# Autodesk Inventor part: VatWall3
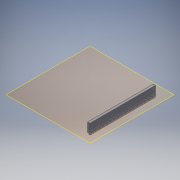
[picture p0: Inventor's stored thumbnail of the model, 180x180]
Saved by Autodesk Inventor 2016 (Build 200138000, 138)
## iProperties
Created: 2015-11
Part Number: VatWall3
Material: Generic
Document SubType Name: Modeling
Designer: John
Density: 1 g/cm^3
Appearance: Default
Author: John
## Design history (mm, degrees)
workplane "Work Plane1"
sketch "Sketch1"
  geometry: L1 (-103.475, 98.475)-(-103.475, -98.475) reference; L2 (-98.475, -103.475)-(98.475, -103.475) reference; L3 (103.475, -98.475)-(103.475, 98.475) reference; L4 (98.475, 103.475)-(-98.475, 103.475) reference; L5 (92.15, 92.15)-(92.15, -92.15) reference; L6 (92.15, -92.15)-(-92.15, -92.15) reference; L7 (-92.15, -92.15)-(-92.15, 92.15) reference; L8 (-92.15, 92.15)-(92.15, 92.15) reference; L9 (88.65, -88.65)-(88.65, 88.65) reference; L10 (88.65, 88.65)-(-88.65, 88.65) reference; L11 (-88.65, 88.65)-(-88.65, -88.65) reference; L12 (-88.65, -88.65)-(88.65, -88.65) reference; L13 (82.3, -85.475)-(-82.3, -85.475) reference; L14 (-85.475, -82.3)-(-85.475, 82.3) reference; L15 (-82.3, 85.475)-(82.3, 85.475) reference; L16 (85.475, 82.3)-(85.475, -82.3) reference; L17 (92.15, 92.15)-(88.65, 92.15); L18 (88.65, 92.15)-(88.65, -92.15); L19 (88.65, -92.15)-(92.15, -92.15); L20 (92.15, -92.15)-(92.15, 92.15); L21 (88.812, -91.988)-(88.812, 91.988); L22 (88.812, 91.988)-(91.987, 91.988); L23 (91.987, 91.988)-(91.987, -91.988); L24 (91.987, -91.988)-(88.812, -91.988); C1 r 1.75 at (-95, 44.824) reference; C2 r 1.75 at (-95, 59.766) reference; C3 r 1.75 at (-95, 29.886) reference; C4 r 1.75 at (-95, -0.002) reference; C5 r 1.75 at (-95, -29.886) reference; C6 r 1.75 at (-95, -59.77) reference; C7 r 1.75 at (-95, -74.708) reference; C8 r 1.75 at (-94.65, 94.65) reference; C9 r 1.75 at (-95, 74.708) reference; C10 r 1.75 at (-95, -44.828) reference; C11 r 1.75 at (-95, -14.944) reference; C12 r 1.75 at (-95, 14.944) reference; C13 r 1.75 at (44.824, 95) reference; C14 r 1.75 at (59.766, 95) reference; C15 r 1.75 at (29.886, 95) reference; C16 r 1.75 at (-0.002, 95) reference; C17 r 1.75 at (-29.886, 95) reference; C18 r 1.75 at (-59.77, 95) reference; C19 r 1.75 at (-74.708, 95) reference; C20 r 1.75 at (74.708, 95) reference; C21 r 1.75 at (-44.828, 95) reference; C22 r 1.75 at (-14.944, 95) reference; C23 r 1.75 at (14.944, 95) reference; C24 r 1.75 at (-14.944, -95) reference; C25 r 1.75 at (14.944, -95) reference; C26 r 1.75 at (44.828, -95) reference; C27 r 1.75 at (-74.708, -95) reference; C28 r 1.75 at (-94.65, -94.65) reference; C29 r 1.75 at (74.708, -95) reference; C30 r 1.75 at (59.77, -95) reference; C31 r 1.75 at (29.886, -95) reference; C32 r 1.75 at (0.002, -95) reference; C33 r 1.75 at (-29.886, -95) reference; C34 r 1.75 at (-59.766, -95) reference; C35 r 1.75 at (-44.824, -95) reference; C36 r 1.75 at (95, -44.824) reference; C37 r 1.75 at (95, -59.766) reference; C38 r 1.75 at (95, -29.886) reference; C39 r 1.75 at (95, 0.002) reference; C40 r 1.75 at (95, 29.886) reference; C41 r 1.75 at (95, 59.77) reference; C42 r 1.75 at (95, 74.708) reference; C43 r 1.75 at (94.65, -94.65) reference; C44 r 1.75 at (94.65, 94.65) reference; C45 r 1.75 at (95, -74.708) reference; C46 r 1.75 at (95, 44.828) reference; C47 r 1.75 at (95, 14.944) reference; C48 r 1.75 at (95, -14.944) reference; A1 r 5 centre (-98.475, 98.475) between (-98.475, 103.475) and (-103.475, 98.475) reference; A2 r 5 centre (-98.475, -98.475) between (-103.475, -98.475) and (-98.475, -103.475) reference; A3 r 5 centre (98.475, -98.475) between (98.475, -103.475) and (103.475, -98.475) reference; A4 r 5 centre (98.475, 98.475) between (103.475, 98.475) and (98.475, 103.475) reference; A5 r 3.175 centre (-82.3, -82.3) between (-85.475, -82.3) and (-82.3, -85.475) reference; A6 r 3.175 centre (-82.3, 82.3) between (-82.3, 85.475) and (-85.475, 82.3) reference; A7 r 3.175 centre (82.3, 82.3) between (85.475, 82.3) and (82.3, 85.475) reference; A8 r 3.175 centre (82.3, -82.3) between (82.3, -85.475) and (85.475, -82.3) reference; 1 further point
  constraints: 16 end point, 4 parallel, 2 perpendicular, 2 point on line, 1 horizontal, 3 other
  dimensions: "d0" = 3.175 distance between parallel lines of L23 L21
extrude "Extrusion1" new body sketch "Sketch1" distance "d1" = 3.175; taper "d2" = 0 deg
sketch "Sketch2"
  geometry: L1 (88.812, -91.988)-(88.812, 91.988) reference; L2 (91.987, -91.988)-(88.812, -91.988) reference; L3 (91.987, 91.988)-(91.987, -91.988) reference; L4 (88.812, 91.988)-(91.987, 91.988) reference; L5 (91.987, 91.988)-(85.637, 91.988); L6 (85.637, 91.988)-(85.637, -91.988); L7 (85.637, -91.988)-(91.987, -91.988); L8 (91.987, -91.988)-(91.987, 91.988); L9 (91.987, -91.988)-(88.812, -91.988) reference; 2 further points
  constraints: 8 end point, 2 midpoint, 2 parallel, 2 point on line, 1 horizontal, 1 perpendicular
  dimensions: "d3" = 6.35 distance of L6.end L7.end
extrude "Extrusion2" join sketch "Sketch2" distance "d4" = 25; taper "d5" = 0 deg
node "Direct Edit1"
body "Solid1"
node "Reference1"
node "Reference2"
node "Projected Loop1"
move_body "Move1" dims "d8" = -6.35
other parameters: "d6" = 0, "d7" = 0
